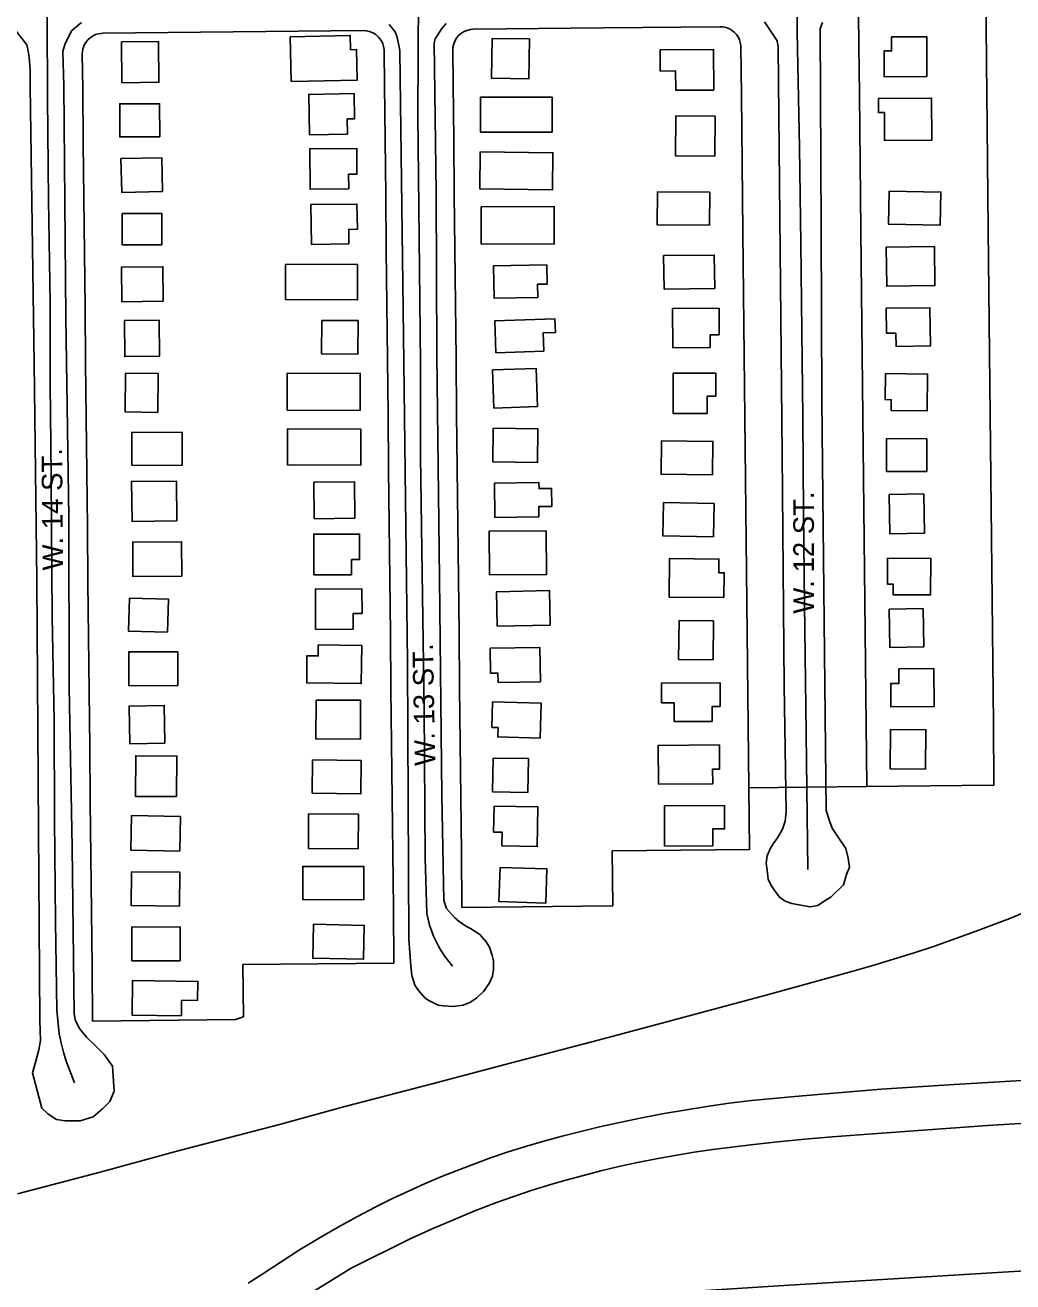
# Model space of a CAD drawing. Extents: x -25029 to 2274964, y -81170 to 687028.
# Drawn here: x -17535 to -16815, y -63741 to -62825 of the extents above; entities that cross this region are included whole.
import ezdxf

# ---------------------------------------------------------------- set-up
doc = ezdxf.new("R2010")
doc.units = 0
for name, color, linetype in [('81911BEA - RW_X_Fee_RW', 7, 'Continuous'), ('BLDG', 7, 'Continuous'), ('GE_X_CL_2000', 7, 'Continuous'), ('INTERSTATE', 7, 'Continuous'), ('ROAD', 7, 'Continuous'), ('ROAD-NAME', 7, 'Continuous')]:
    doc.layers.add(name, color=color, linetype=linetype)

msp = doc.modelspace()

# ---------------------------------------------------------------- linework, layer by layer
at = {"layer": '81911BEA - RW_X_Fee_RW'}
for p, q in [((-17208.85, -62827.75), (-17113.9, -62826.73)), ((-17113.9, -62826.73), (-17028.9, -62825.82)), ((-17107.48, -63426.69), (-17007.49, -63425.62)), ((-17107.48, -63426.69), (-17107.05, -63466.7)), ((-17217, -63467.87), (-17107.05, -63466.7)), ((-17266.57, -63508.41), (-17376.57, -63509.5)), ((-17376.57, -63509.5), (-17376.16, -63547.58)), ((-17486.14, -63550.76), (-17382.14, -63549.64)), ((-17382.14, -63549.64), (-17376.16, -63547.58))]:
    msp.add_line(p, q, dxfattribs=at)
for points in [[(-16928.13, -62799.74), (-16927.62, -62837.13), (-16927.65, -62837.78), (-16927.7, -62839.74), (-16927.33, -62874.73), (-16926.79, -62924.73), (-16926.26, -62974.73), (-16925.78, -63019.73), (-16925.3, -63064.72), (-16924.81, -63109.72), (-16924.33, -63154.72), (-16923.85, -63199.72), (-16923.37, -63244.71), (-16922.89, -63289.71), (-16922.41, -63334.71), (-16921.93, -63379.71)], [(-16834.73, -62852.72), (-16835.04, -62823.74), (-16835.14, -62813.55)], [(-17478.84, -62830.64), (-17383.85, -62829.62), (-17288.85, -62828.6)], [(-17273.69, -62843.44), (-17273.74, -62842.46), (-17274.09, -62840.2), (-17274.65, -62838.32), (-17275.47, -62836.54), (-17276.49, -62834.87), (-17277.75, -62833.36), (-17279.69, -62831.62), (-17281.91, -62830.24), (-17284.33, -62829.26), (-17286.89, -62828.73), (-17288.85, -62828.6)], [(-17208.85, -62827.75), (-17210.81, -62827.91), (-17213.35, -62828.5), (-17215.75, -62829.53), (-17217.94, -62830.96), (-17219.41, -62832.26), (-17220.68, -62833.75), (-17222.06, -62835.97), (-17223.03, -62838.4), (-17223.57, -62840.95), (-17223.69, -62842.91)], [(-17013.74, -62840.65), (-17013.79, -62839.67), (-17014.14, -62837.41), (-17014.7, -62835.53), (-17015.52, -62833.75), (-17016.95, -62831.57), (-17018.25, -62830.1), (-17019.74, -62828.83), (-17021.96, -62827.45), (-17024.39, -62826.48), (-17026.94, -62825.94), (-17028.9, -62825.82)], [(-17478.84, -62830.64), (-17479.82, -62830.69), (-17482.08, -62831.04), (-17483.96, -62831.6), (-17485.74, -62832.42), (-17487.93, -62833.85), (-17489.4, -62835.14), (-17490.67, -62836.64), (-17491.75, -62838.28), (-17492.59, -62840.05), (-17493.21, -62841.91), (-17493.56, -62843.84), (-17493.68, -62845.8)], [(-17486.14, -63550.76), (-17486.57, -63510.76), (-17487, -63470.76), (-17487.42, -63430.76), (-17487.85, -63390.77), (-17488.28, -63350.77), (-17488.71, -63310.77), (-17489.14, -63270.77), (-17489.56, -63230.77), (-17489.99, -63190.78), (-17490.42, -63150.78), (-17490.85, -63110.78), (-17491.27, -63070.78), (-17491.7, -63030.79), (-17492.13, -62990.79), (-17492.56, -62950.79), (-17492.99, -62910.79), (-17493.41, -62870.8), (-17493.68, -62845.8)], [(-17266.57, -63508.41), (-17267, -63468.41), (-17267.43, -63428.41), (-17267.86, -63388.41), (-17268.29, -63348.42), (-17268.71, -63308.42), (-17269.14, -63268.42), (-17269.57, -63228.42), (-17270, -63188.42), (-17270.43, -63148.43), (-17270.85, -63108.43), (-17271.28, -63068.43), (-17271.71, -63028.43), (-17272.14, -62988.44), (-17272.56, -62948.44), (-17272.99, -62908.44), (-17273.42, -62868.44), (-17273.69, -62843.44)], [(-17217, -63467.87), (-17217.43, -63427.88), (-17217.86, -63387.88), (-17218.29, -63347.88), (-17218.72, -63307.88), (-17219.14, -63267.89), (-17219.57, -63227.89), (-17220, -63187.89), (-17220.43, -63147.89), (-17220.86, -63107.89), (-17221.28, -63067.9), (-17221.71, -63027.9), (-17222.14, -62987.9), (-17222.57, -62947.9), (-17222.99, -62907.9), (-17223.42, -62867.91), (-17223.69, -62842.91)], [(-17013.74, -62840.65), (-17013.37, -62875.65), (-17012.83, -62925.65), (-17012.3, -62975.65), (-17011.82, -63020.64), (-17011.33, -63065.64), (-17010.85, -63110.64), (-17010.37, -63155.64), (-17009.89, -63200.64), (-17009.41, -63245.63), (-17008.93, -63290.63), (-17008.45, -63335.63), (-17007.97, -63380.63), (-17007.49, -63425.62)], [(-16829.23, -63378.71), (-16829.7, -63333.72), (-16830.17, -63288.72), (-16830.64, -63243.72), (-16831.11, -63198.72), (-16831.59, -63153.73), (-16832.06, -63108.73), (-16832.53, -63063.73), (-16833, -63018.73), (-16833.47, -62973.74), (-16833.99, -62923.74), (-16834.51, -62873.74), (-16834.73, -62852.72)], [(-16829.23, -63378.71), (-16921.93, -63379.71), (-17007.97, -63380.63)]]:
    msp.add_lwpolyline(points, dxfattribs=at)
at = {"layer": 'BLDG'}
for points in [[(-17465.2, -62836.96), (-17464.78, -62866.69), (-17437.8, -62866.31), (-17438.22, -62836.58)], [(-17341.4, -62865.82), (-17293.27, -62864.79), (-17293.75, -62842.52), (-17298.15, -62842.61), (-17298.37, -62832.19), (-17342.1, -62833.12)], [(-17195, -62834.38), (-17195.42, -62863.43), (-17168.21, -62863.82), (-17167.79, -62834.78)], [(-16903.89, -62833.22), (-16903.87, -62843.45), (-16909.37, -62843.46), (-16909.35, -62862.29), (-16878.24, -62862.25), (-16878.28, -62833.18)], [(-17072.65, -62842.73), (-17072.58, -62858.14), (-17061.27, -62858.09), (-17061.21, -62872.17), (-17033.47, -62872.05), (-17033.6, -62842.56)], [(-17300.45, -62904.14), (-17300.65, -62893.01), (-17295.24, -62892.91), (-17295.56, -62874.64), (-17328.7, -62875.22), (-17328.18, -62904.62)], [(-17437.28, -62906.1), (-17437.33, -62881.97), (-17466.4, -62882.04), (-17466.35, -62906.16)], [(-17203.41, -62902.61), (-17151.27, -62902.64), (-17151.26, -62877.2), (-17203.39, -62877.17)], [(-16913.5, -62878.17), (-16913.42, -62888.48), (-16909.09, -62888.45), (-16908.93, -62908.82), (-16874.5, -62908.55), (-16874.75, -62877.86)], [(-17032.79, -62920.26), (-17032.54, -62891.11), (-17061.06, -62890.87), (-17061.31, -62920.02)], [(-17299.49, -62944.1), (-17299.58, -62933.43), (-17293.51, -62933.37), (-17293.68, -62914.53), (-17327.94, -62914.83), (-17327.67, -62944.35)], [(-17151.07, -62944.69), (-17150.68, -62917.72), (-17203.66, -62916.95), (-17204.05, -62943.92)], [(-17435.25, -62945.95), (-17435.81, -62921.31), (-17465.51, -62921.98), (-17464.95, -62946.63)], [(-17036.64, -62970.59), (-17036.44, -62946.49), (-17074.44, -62946.19), (-17074.63, -62970.28)], [(-16905.63, -62945.64), (-16906.13, -62969.67), (-16868.36, -62970.46), (-16867.86, -62946.43)], [(-17299.32, -62984.12), (-17299.47, -62973.64), (-17293.23, -62973.55), (-17293.49, -62955.1), (-17327.09, -62955.57), (-17326.68, -62984.51)], [(-17202.89, -62984.25), (-17149.72, -62984.15), (-17149.77, -62957.02), (-17202.94, -62957.12)], [(-17435.72, -62984.78), (-17435.75, -62961.99), (-17464.57, -62962.03), (-17464.53, -62984.83)], [(-17032.8, -63016.61), (-17033.1, -62992.27), (-17070, -62992.72), (-17069.71, -63017.06)], [(-16907.82, -62986.59), (-16907.41, -63015.06), (-16872.23, -63014.56), (-16872.63, -62986.09)], [(-17434.71, -63025.99), (-17434.97, -63000.86), (-17465.17, -63001.17), (-17464.92, -63026.3)], [(-17345.48, -62998.99), (-17345.54, -63024.82), (-17293.09, -63024.96), (-17293.02, -62999.13)], [(-17161.78, -63023.28), (-17161.93, -63013.52), (-17154.93, -63013.41), (-17155.14, -62999.49), (-17193.99, -63000.08), (-17193.63, -63023.76)], [(-17157.38, -63062.42), (-17157.82, -63049.11), (-17148.89, -63048.81), (-17149.22, -63038.82), (-17193.07, -63040.28), (-17192.3, -63063.58)], [(-17036.03, -63059.81), (-17036.08, -63050.42), (-17029.54, -63050.38), (-17029.65, -63031.12), (-17063.45, -63031.31), (-17063.29, -63059.96)], [(-16907.77, -63031.11), (-16907.53, -63049.35), (-16900.68, -63049.26), (-16900.55, -63058.94), (-16875.55, -63058.6), (-16875.93, -63030.67)], [(-17437.48, -63066.01), (-17437.74, -63039.81), (-17463.01, -63040.06), (-17462.75, -63066.26)], [(-17319.23, -63039.98), (-17319.35, -63064.4), (-17292.83, -63064.54), (-17292.7, -63040.12)], [(-17162.03, -63102.68), (-17163.02, -63074.9), (-17194.64, -63076.02), (-17193.65, -63103.81)], [(-17438.71, -63106.97), (-17438.37, -63078.66), (-17462.09, -63078.38), (-17462.42, -63106.68)], [(-17344.31, -63078.3), (-17344.43, -63105.28), (-17291.18, -63105.51), (-17291.06, -63078.53)], [(-17038.18, -63107.78), (-17038.17, -63095.15), (-17032.06, -63095.16), (-17032.05, -63078.4), (-17063.05, -63078.38), (-17063.07, -63107.77)], [(-16908.41, -63078.74), (-16908.62, -63097.68), (-16904.11, -63097.73), (-16904.2, -63105.62), (-16877.88, -63105.91), (-16877.58, -63079.09)], [(-17421.01, -63145.65), (-17420.86, -63121.62), (-17457.53, -63121.4), (-17457.68, -63145.43)], [(-17344.05, -63119.01), (-17344.2, -63145.26), (-17290.77, -63145.56), (-17290.62, -63119.3)], [(-17194.14, -63118.52), (-17194.58, -63143.02), (-17162.02, -63143.6), (-17161.58, -63119.1)], [(-17034.29, -63152.46), (-17034.08, -63128.17), (-17071.6, -63127.85), (-17071.81, -63152.14)], [(-16907.52, -63126.15), (-16907.54, -63150.16), (-16878.21, -63150.18), (-16878.18, -63126.18)], [(-17424.74, -63186.08), (-17425.14, -63157.03), (-17457.84, -63157.47), (-17457.45, -63186.52)], [(-17295.1, -63184.23), (-17295.33, -63157.59), (-17324.89, -63157.85), (-17324.66, -63184.49)], [(-17160.95, -63183.08), (-17161.05, -63175.65), (-17151.5, -63175.53), (-17151.67, -63162.39), (-17160.81, -63162.51), (-17160.87, -63158.04), (-17193.26, -63158.48), (-17192.92, -63183.51)], [(-16879.96, -63195.15), (-16880.44, -63166.48), (-16905.57, -63166.9), (-16905.09, -63195.56)], [(-17033.64, -63197.74), (-17033.16, -63173.49), (-17070.1, -63172.77), (-17070.58, -63197.01)], [(-17197.03, -63225.38), (-17155.44, -63225.18), (-17155.59, -63193.4), (-17197.18, -63193.6)], [(-17421.24, -63226.44), (-17421.39, -63201.33), (-17456.89, -63201.54), (-17456.74, -63226.66)], [(-17297.43, -63225.3), (-17297.45, -63214.32), (-17291.56, -63214.31), (-17291.59, -63195.7), (-17324.98, -63195.75), (-17324.93, -63225.35)], [(-17026.01, -63241.95), (-17025.88, -63223.91), (-17029.78, -63223.89), (-17029.71, -63213.89), (-17065.74, -63213.63), (-17065.94, -63241.67)], [(-16906.75, -63213.3), (-16906.81, -63232.25), (-16902.66, -63232.26), (-16902.68, -63239.98), (-16875.45, -63240.07), (-16875.36, -63213.41)], [(-17296.29, -63265), (-17296.35, -63253.63), (-17289.81, -63253.59), (-17289.92, -63235.63), (-17323.79, -63235.83), (-17323.62, -63265.16)], [(-17152.62, -63262.16), (-17153.15, -63236.94), (-17191.76, -63237.75), (-17191.23, -63262.96)], [(-17431.48, -63267.17), (-17430.82, -63243.22), (-17459.36, -63242.43), (-17460.02, -63266.38)], [(-16905.75, -63250.41), (-16905.25, -63278.35), (-16880.4, -63277.91), (-16880.89, -63249.97)], [(-17058.76, -63258.73), (-17059.05, -63287.04), (-17034.02, -63287.29), (-17033.73, -63258.98)], [(-17321.7, -63276.53), (-17321.78, -63284.5), (-17329.95, -63284.42), (-17330.15, -63304.25), (-17290.36, -63304.66), (-17290.07, -63276.85)], [(-17423.97, -63306.09), (-17424.1, -63281.45), (-17459.87, -63281.65), (-17459.74, -63306.29)], [(-17196.32, -63278.97), (-17196.07, -63297.1), (-17190.73, -63297.03), (-17190.63, -63303.82), (-17159.81, -63303.38), (-17160.16, -63278.46)], [(-16898.56, -63293.86), (-16898.5, -63304.58), (-16904.49, -63304.62), (-16904.39, -63321.67), (-16872.9, -63321.5), (-16873.06, -63293.72)], [(-17071.45, -63318.81), (-17062.26, -63318.78), (-17062.22, -63332.3), (-17034.65, -63332.23), (-17034.68, -63321.32), (-17028.87, -63321.3), (-17028.92, -63304.25), (-17071.49, -63304.37)], [(-17433.45, -63348.2), (-17433.98, -63320.66), (-17459.55, -63321.15), (-17459.02, -63348.69)], [(-17323.34, -63316.8), (-17323.4, -63345.06), (-17290.98, -63345.13), (-17290.92, -63316.87)], [(-17194.67, -63318.02), (-17195.14, -63336.66), (-17190.68, -63336.77), (-17190.85, -63343.61), (-17160.02, -63344.38), (-17159.38, -63318.91)], [(-16879.15, -63367.06), (-16878.87, -63338.35), (-16904.55, -63338.09), (-16904.84, -63366.8)], [(-17034.24, -63377.66), (-17034.32, -63367.03), (-17029.26, -63366.99), (-17029.39, -63349.39), (-17074.03, -63349.73), (-17073.82, -63377.97)], [(-17424.92, -63387.11), (-17424.73, -63357.53), (-17454.76, -63357.35), (-17454.95, -63386.93)], [(-17290.37, -63360.69), (-17325.92, -63360.35), (-17326.15, -63384.68), (-17290.6, -63385.02)], [(-17194.27, -63359.02), (-17194.67, -63383.59), (-17168.99, -63384), (-17168.59, -63359.43)], [(-17193.55, -63394), (-17193.88, -63412.91), (-17187.68, -63413.02), (-17187.86, -63423.06), (-17162.16, -63423.51), (-17161.66, -63394.55)], [(-17034.13, -63422.91), (-17034.2, -63410.64), (-17025.55, -63410.59), (-17025.66, -63393.49), (-17069.48, -63393.76), (-17069.3, -63423.13)], [(-17422.58, -63426.76), (-17422.2, -63401.5), (-17457.89, -63400.95), (-17458.28, -63426.21)], [(-17328.81, -63399.74), (-17328.92, -63424.91), (-17292.54, -63425.08), (-17292.42, -63399.91)], [(-17422.9, -63466.92), (-17422.67, -63442.13), (-17457.76, -63441.81), (-17457.99, -63466.59)], [(-17288.55, -63462.22), (-17288.54, -63437.99), (-17333.07, -63437.98), (-17333.08, -63462.21)], [(-17189.15, -63438.66), (-17190.02, -63463.56), (-17155.9, -63464.75), (-17155.04, -63439.84)], [(-17422.36, -63506.78), (-17422.44, -63482.07), (-17457.65, -63482.18), (-17457.57, -63506.89)], [(-17325.24, -63480.17), (-17325.77, -63504.89), (-17288.72, -63505.68), (-17288.19, -63480.96)], [(-17421.47, -63546.82), (-17421.32, -63535.55), (-17409.65, -63535.71), (-17409.46, -63521.76), (-17457.05, -63521.12), (-17457.39, -63546.33)]]:
    msp.add_lwpolyline(points, close=True, dxfattribs=at)
at = {"layer": 'GE_X_CL_2000'}
for points in [[(-16972.69, -62798.78), (-16972.59, -62829.91), (-16971.03, -62913.85), (-16969.89, -62983.6), (-16969.22, -63047.81), (-16968.59, -63110.78), (-16968.07, -63180.55), (-16967.33, -63246.9), (-16966.35, -63321.61), (-16965, -63440.13)], [(-17519.51, -62806.04), (-17519.22, -62819.56), (-17519.04, -62877.9), (-17518.38, -62951.97), (-17517.08, -63027.27), (-17517.17, -63086.55), (-17516.67, -63129.79), (-17516.39, -63154.75), (-17515.54, -63255.99), (-17514.24, -63331.28), (-17513.94, -63403.82), (-17513.27, -63478.21), (-17512.29, -63542.7), (-17510.54, -63559.93), (-17509.05, -63566.63), (-17507.31, -63573.27), (-17505.33, -63579.85), (-17503.1, -63586.35), (-17499.36, -63595.8)], [(-17248.74, -62802.36), (-17249.06, -62890.58), (-17248.27, -62979.87), (-17247.1, -63071.61), (-17247.26, -63138.99), (-17245.98, -63224.25), (-17244.59, -63323.09), (-17243.83, -63431.85), (-17242.63, -63472.3), (-17241.71, -63476.52), (-17240.56, -63480.69), (-17239.19, -63484.79), (-17237.61, -63488.81), (-17235.82, -63492.75), (-17233.82, -63496.58), (-17231.62, -63500.3), (-17229.22, -63503.9), (-17226.64, -63507.36), (-17223.88, -63510.69)], [(-16807.29, -63471.59), (-16817.67, -63475.83), (-16842.92, -63485.47), (-16857.71, -63490.84), (-16872.58, -63496), (-16887.52, -63500.94), (-16902.52, -63505.68), (-16917.6, -63510.19), (-16932.77, -63514.51), (-16993.53, -63531.4), (-17065.05, -63550.46), (-17117.61, -63564.65), (-17181.82, -63581.34), (-17238.68, -63596.59), (-17302.32, -63612.96), (-17350.01, -63626.09), (-17423.7, -63645.23), (-17480.58, -63660.79), (-17540.8, -63676.74)], [(-16788.35, -63592.79), (-16858.19, -63597.03), (-16911.43, -63600.47), (-16942.96, -63602.92), (-16974.44, -63605.61), (-17005.99, -63608.56), (-17022.35, -63610.65), (-17038.61, -63613), (-17054.84, -63615.59), (-17071.03, -63618.43), (-17087.17, -63621.52), (-17103.26, -63624.87), (-17116.83, -63627.89), (-17130.37, -63631.15), (-17143.84, -63634.62), (-17157.26, -63638.31), (-17170.62, -63642.21), (-17183.95, -63646.35), (-17196.19, -63650.53), (-17208.33, -63654.93), (-17220.38, -63659.54), (-17232.33, -63664.37), (-17244.22, -63669.42), (-17256, -63674.67), (-17267.68, -63680.14), (-17279.34, -63685.86), (-17293.58, -63693.47), (-17307.63, -63701.28), (-17321.58, -63709.31), (-17335.39, -63717.58), (-17362.1, -63734.98), (-17372.92, -63741.67)], [(-17324.5, -63747.39), (-17297.74, -63730.82), (-17254.37, -63709.19), (-17238.82, -63702.23), (-17223.26, -63695.62), (-17207.71, -63689.13), (-17191.8, -63682.88), (-17179.23, -63678.49), (-17166.65, -63674.34), (-17153.96, -63670.43), (-17141.27, -63666.63), (-17128.46, -63663.19), (-17115.66, -63659.87), (-17102.74, -63656.79), (-17088.99, -63653.83), (-17075.36, -63651.11), (-17061.62, -63648.62), (-17047.87, -63646.38), (-17034.13, -63644.37), (-17020.28, -63642.59), (-17006.54, -63641.05), (-16986.89, -63638.86), (-16967.11, -63636.9), (-16947.22, -63635.18), (-16927.46, -63633.57), (-16907.69, -63632.2), (-16834.06, -63626.92), (-16750.26, -63621.73)]]:
    msp.add_lwpolyline(points, dxfattribs=at)
at = {"layer": 'INTERSTATE'}
msp.add_lwpolyline([(-15802.26, -63834.96), (-15947.69, -63791.83), (-16066.92, -63765.51), (-16204.64, -63742.78), (-16303.64, -63731.43), (-16391.9, -63724.76), (-16502.66, -63721.47), (-16622.99, -63723.42), (-16742.84, -63728.86), (-16982.52, -63743.47), (-17202.17, -63757.5), (-17341.37, -63766.6), (-17561.06, -63780.03), (-17760.1, -63792.87), (-17851.59, -63798.78)], dxfattribs=at)
at = {"layer": 'ROAD'}
for points in [[(-17547.05, -62822.61), (-17534.17, -62838.97), (-17533.41, -62842.13), (-17532.4, -62848.01), (-17531.61, -62857.35), (-17531.78, -62869.45), (-17528.69, -63071.23), (-17526.89, -63229.05), (-17525.57, -63411.43), (-17524.61, -63550.21), (-17524.15, -63564.85), (-17525.47, -63571.65), (-17527.57, -63580), (-17529.97, -63588.54), (-17523.25, -63614.23), (-17518.69, -63618.28), (-17512.45, -63622.52), (-17506.18, -63623.49), (-17495.34, -63623.51), (-17485.71, -63620.63), (-17478.92, -63614.67), (-17473.64, -63609.36), (-17470.5, -63601.79), (-17471.74, -63583.59), (-17477.79, -63575.19), (-17484.52, -63568.4), (-17490.54, -63562.38), (-17495.83, -63556.16), (-17498.73, -63550.57), (-17499.69, -63545.34), (-17500.97, -63423.84), (-17503.23, -63307.67), (-17503.47, -63183.42), (-17505.63, -63037.93), (-17507.16, -62868.6), (-17507.87, -62844.01), (-17506.28, -62838.2), (-17501.3, -62828.63), (-17494.16, -62822.89)], [(-17270, -62824.24), (-17265.6, -62829.49), (-17264.18, -62833.57), (-17263.4, -62837.01), (-17262.41, -62841.61), (-17262.24, -62843.91), (-17259.65, -63050.89), (-17256.67, -63289.04), (-17255.74, -63491.01), (-17254.28, -63510.37), (-17253.43, -63517.54), (-17251.24, -63524.49), (-17248.71, -63528.47), (-17244.11, -63533.74), (-17241.52, -63535.5), (-17234.42, -63539.11), (-17230.58, -63539.72), (-17223.25, -63540.05), (-17216.17, -63539.23), (-17210.79, -63536.91), (-17206.15, -63533.72), (-17201.36, -63529.06), (-17197.16, -63523.33), (-17194.79, -63517.95), (-17193.99, -63513.23), (-17193.93, -63506.74), (-17194.89, -63502.9), (-17196.81, -63496.96), (-17199.26, -63492.93), (-17203.92, -63487.63), (-17210.74, -63483.12), (-17214.18, -63481.5), (-17219, -63478.03), (-17222.14, -63475.38), (-17224.66, -63472.68), (-17228.16, -63468.65), (-17229.23, -63465.79), (-17230.13, -63462.89), (-17231.61, -63386.05), (-17233.26, -63227.76), (-17235.41, -63065.28), (-17235.9, -62946.62), (-17237.25, -62837.65), (-17236.44, -62834.77), (-17235.07, -62832.53), (-17231.56, -62827.11), (-17228.47, -62823.56)], [(-16996.58, -62822.19), (-16987.15, -62836.05), (-16986.48, -62840.67), (-16983.59, -63137.45), (-16982.2, -63306.1), (-16980.74, -63398.15), (-16981.46, -63405.06), (-16983.39, -63410.79), (-16987.07, -63417.15), (-16990.07, -63421.42), (-16992.06, -63424.67), (-16994.59, -63430.37), (-16995.18, -63435.6), (-16994.62, -63440.7), (-16993.71, -63447.22), (-16991.97, -63451.34), (-16989.41, -63455.14), (-16985.47, -63460.35), (-16981.41, -63463.37), (-16976.48, -63465.13), (-16963.33, -63467.48), (-16957.65, -63466.48), (-16953.04, -63463.3), (-16947.91, -63460.24), (-16938.95, -63451.3), (-16936.68, -63443.99), (-16934.57, -63438.54), (-16935.57, -63431.86), (-16937.19, -63424.97), (-16943.37, -63415.85), (-16947.25, -63410.16), (-16948.95, -63405.55), (-16951.46, -63397.25), (-16954.7, -63098.4), (-16955.28, -62972.77), (-16955.8, -62827.03), (-16954.33, -62822.82)]]:
    msp.add_lwpolyline(points, dxfattribs=at)

# ---------------------------------------------------------------- texts
at = {"layer": 'ROAD-NAME'}
for s, height, rotation, p in [('W. 14 ST.', 15, 90.53991, (-17507.6, -63222.13)), ('W. 12 ST.', 14.99, 90.02081, (-16960.46, -63253.73)), ('W. 13 ST.', 15, 91.15077, (-17236.35, -63364.48))]:
    msp.add_text(s, height=height, rotation=rotation, dxfattribs=at).set_placement(p)

doc.saveas('drawing.dxf')
